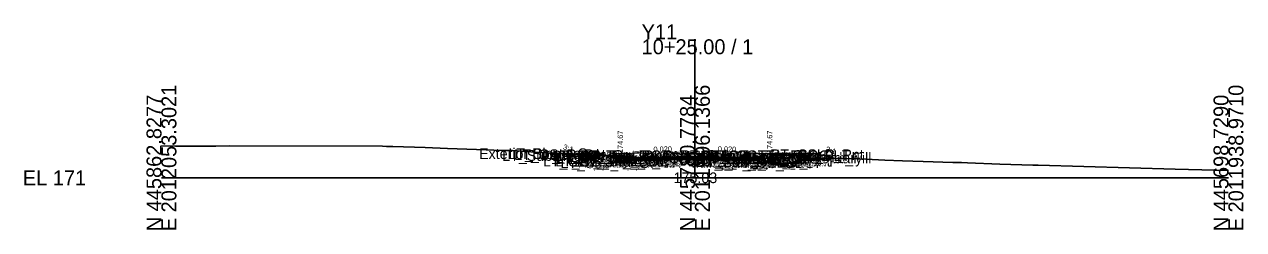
# Model space of a CAD drawing. Extents: x -26 to 203, y -10 to 3517.
# Drawn here: x -25.7 to 202.8, y 490.3 to 528.8 of the extents above; entities that cross this region are included whole.
import ezdxf

# ---------------------------------------------------------------- set-up
doc = ezdxf.new("R2010")
doc.units = 0
for name, color, linetype in [('Default', 7, 'Continuous'), ('Exist CMT Pavement', 7, 'Continuous'), ('Exist Cross Section Cell', 7, 'Continuous'), ('Exist XS Center Line Elevation Label', 7, 'Continuous'), ('Exist XS Ground Line', 7, 'Continuous'), ('Prop CMT Conc Surface', 7, 'Continuous'), ('Prop CMT Concrete Structures', 7, 'Continuous'), ('Prop CMT Pvmt Course 1', 7, 'Continuous'), ('Prop CMT Pvmt Course 1 CG', 7, 'Continuous'), ('Prop CMT Pvmt Course 1 Wedge', 7, 'Continuous'), ('Prop CMT Pvmt Course 2', 7, 'Continuous'), ('Prop CMT Pvmt Course 2 Wedge', 7, 'Continuous'), ('Prop CMT Pvmt Course 3', 7, 'Continuous'), ('Prop CMT Pvmt Course 3 Wedge', 7, 'Continuous'), ('Prop CMT Pvmt Surface', 7, 'Continuous'), ('Prop CMT Pvmt Wedge Surface 1', 7, 'Continuous'), ('Prop CMT Pvmt Wedge Surface 2', 7, 'Continuous'), ('Prop CMT Pvmt Wedge Surface 3', 7, 'Continuous'), ('Prop CMT Slope Grass', 7, 'Continuous'), ('Prop CMT Subgrade Earthwork', 7, 'Continuous'), ('Prop XS Earthwork Shape', 7, 'Continuous'), ('Prop XS Hydro Elevations', 7, 'Continuous'), ('Prop XS SE Text', 7, 'Continuous'), ('Prop XS Side Slope Text', 7, 'Continuous'), ('Scratch_Level_0', 7, 'Continuous')]:
    doc.layers.add(name, color=color, linetype=linetype)

msp = doc.modelspace()

# ---------------------------------------------------------------- linework, layer by layer
at = {"layer": 'Exist CMT Pavement'}
for points in [[(100, 504.03), (89.31, 503.79), (89, 503.83)], [(100, 504.03), (100.5, 504.04), (111, 503.73)]]:
    msp.add_lwpolyline(points, dxfattribs=at)
at = {"layer": 'Exist Cross Section Cell'}
for p, q in [((100, 500), (100, 526.01)), ((0, 500), (100, 500)), ((100, 500), (200, 500))]:
    msp.add_line(p, q, dxfattribs=at)
at = {"layer": 'Exist XS Ground Line'}
msp.add_lwpolyline([(0, 506), (2.65, 505.99), (8.91, 505.97), (10.21, 505.97), (12.8, 506), (41.41, 505.94), (42.21, 505.93), (43.37, 505.9), (49.4, 505.73), (53.6, 505.55), (60.86, 505.29), (63.76, 505.16), (65.79, 505.14), (70.95, 504.76), (85.86, 504.1), (87.28, 504.02), (87.87, 503.98), (89.31, 503.79), (89.65, 503.79), (96.56, 503.95), (100, 504.03), (100.5, 504.04), (112.54, 503.68), (113.41, 503.8), (128.42, 503.68), (130.84, 503.58), (135.6, 503.36), (138.92, 503.2), (142.79, 503.06), (148.34, 502.91), (149.97, 502.89), (151.11, 502.83), (157.16, 502.61), (163.3, 502.43), (164.34, 502.37), (190.01, 501.63), (200, 501.41)], dxfattribs=at)
at = {"layer": 'Prop CMT Conc Surface'}
for points in [[(86, 503.67), (86, 504.17), (85.5, 504.17)], [(88, 503.79), (86, 503.67)], [(112, 503.79), (114, 503.67)], [(114, 503.67), (114, 504.17), (114.5, 504.17)]]:
    msp.add_lwpolyline(points, dxfattribs=at)
at = {"layer": 'Prop CMT Concrete Structures'}
for points in [[(88, 503.79), (86, 503.67), (86, 504.17), (85.5, 504.17)], [(85.5, 504.17), (85.5, 503.16), (88, 503.21)], [(88, 503.21), (88, 503.79)], [(112, 503.79), (114, 503.67), (114, 504.17), (114.5, 504.17)], [(114.5, 504.17), (114.5, 503.16), (112, 503.21)], [(112, 503.21), (112, 503.79)]]:
    msp.add_lwpolyline(points, dxfattribs=at)
at = {"layer": 'Prop CMT Pvmt Course 1'}
for points in [[(100, 504.03), (88, 503.79)], [(88, 503.79), (88, 503.54)], [(88, 503.54), (89, 503.56)], [(89, 503.69), (100, 503.91)], [(89, 503.56), (89, 503.69)], [(100, 503.78), (100, 504.03)], [(100, 504.03), (112, 503.79)], [(100, 503.78), (100, 504.03)], [(100, 503.91), (100, 503.78), (100, 503.78)], [(111, 503.69), (100, 503.91)], [(100, 503.91), (100, 503.78), (100, 503.78)], [(111, 503.56), (111, 503.69)], [(112, 503.54), (111, 503.56)], [(112, 503.79), (112, 503.54)]]:
    msp.add_lwpolyline(points, dxfattribs=at)
at = {"layer": 'Prop CMT Pvmt Course 1 CG'}
for points in [[(88, 503.21), (85, 503.15), (84.7, 502.85)], [(84.7, 502.85), (88, 502.92)], [(88, 502.92), (88, 503.21)], [(112, 503.21), (115, 503.15), (115.3, 502.85)], [(112, 502.92), (112, 503.21)], [(115.3, 502.85), (112, 502.92)]]:
    msp.add_lwpolyline(points, dxfattribs=at)
at = {"layer": 'Prop CMT Pvmt Course 1 Wedge'}
for points in [[(100, 503.91), (89, 503.69)], [(100, 503.91), (111, 503.69)]]:
    msp.add_lwpolyline(points, dxfattribs=at)
at = {"layer": 'Prop CMT Pvmt Course 2'}
for points in [[(89, 503.56), (88, 503.54)], [(88, 503.54), (88, 503.29)], [(88, 503.29), (89, 503.31)], [(89, 503.31), (89, 503.56)], [(111, 503.31), (111, 503.56)], [(111, 503.56), (112, 503.54)], [(112, 503.29), (111, 503.31)], [(112, 503.54), (112, 503.29)]]:
    msp.add_lwpolyline(points, dxfattribs=at)
at = {"layer": 'Prop CMT Pvmt Course 2 Wedge'}
for points in [[(100, 503.78), (89, 503.56)], [(100, 503.78), (111, 503.56)]]:
    msp.add_lwpolyline(points, dxfattribs=at)
at = {"layer": 'Prop CMT Pvmt Course 3'}
for points in [[(89, 503.31), (88, 503.29)], [(88, 503.29), (88, 502.92)], [(88, 502.92), (89, 502.94)], [(89, 502.94), (89, 503.31)], [(111, 503.31), (112, 503.29)], [(111, 502.94), (111, 503.31)], [(112, 502.92), (111, 502.94)], [(112, 503.29), (112, 502.92)]]:
    msp.add_lwpolyline(points, dxfattribs=at)
at = {"layer": 'Prop CMT Pvmt Course 3 Wedge'}
for points in [[(100, 503.53), (89, 503.31)], [(100, 503.53), (111, 503.31)]]:
    msp.add_lwpolyline(points, dxfattribs=at)
at = {"layer": 'Prop CMT Pvmt Surface'}
for points in [[(100, 504.03), (88, 503.79)], [(100, 504.03), (112, 503.79)]]:
    msp.add_lwpolyline(points, dxfattribs=at)
at = {"layer": 'Prop CMT Pvmt Wedge Surface 1'}
for points in [[(88, 503.54), (88, 503.79)], [(89, 503.56), (88, 503.54)], [(100, 503.91), (89, 503.69)], [(89, 503.69), (89, 503.56)], [(100, 503.91), (111, 503.69)], [(111, 503.69), (111, 503.56)], [(111, 503.56), (112, 503.54)], [(112, 503.54), (112, 503.79)]]:
    msp.add_lwpolyline(points, dxfattribs=at)
at = {"layer": 'Prop CMT Pvmt Wedge Surface 2'}
for points in [[(88, 503.54), (88, 503.79)], [(100, 503.78), (88, 503.54)], [(100, 503.78), (112, 503.54)], [(112, 503.54), (112, 503.79)]]:
    msp.add_lwpolyline(points, dxfattribs=at)
at = {"layer": 'Prop CMT Pvmt Wedge Surface 3'}
for points in [[(88, 503.29), (88, 503.79)], [(100, 503.53), (88, 503.29)], [(100, 503.53), (112, 503.29)], [(112, 503.29), (112, 503.79)]]:
    msp.add_lwpolyline(points, dxfattribs=at)
at = {"layer": 'Prop CMT Slope Grass'}
for points in [[(85.5, 504.17), (76, 504.36), (75.39, 504.57)], [(114.5, 504.17), (124, 504.36), (125.97, 503.7)]]:
    msp.add_lwpolyline(points, dxfattribs=at)
at = {"layer": 'Prop CMT Subgrade Earthwork'}
for points in [[(88, 502.92), (84.7, 502.85), (83.34, 504.21)], [(89, 502.94), (88, 502.92)], [(89, 502.94), (89, 503.83)], [(111, 502.94), (111, 503.73)], [(111, 502.94), (112, 502.92)], [(112, 502.92), (115.3, 502.85), (116.66, 504.21)]]:
    msp.add_lwpolyline(points, dxfattribs=at)
at = {"layer": 'Prop XS Earthwork Shape'}
for points in [[(75.39, 504.57), (83.34, 504.21), (76, 504.36)], [(83.34, 504.21), (85.5, 504.12), (85.5, 503.16), (88, 503.21), (88, 503.79), (89, 503.81), (89, 502.94), (88, 502.92), (84.7, 502.85)], [(85.86, 504.1), (86, 504.09), (86, 503.67), (88, 503.79), (88, 503.21), (85.5, 503.16), (85.5, 504.12)], [(89, 503.81), (89, 503.83), (87.87, 503.98), (87.28, 504.02), (86, 504.09), (86, 503.67), (88, 503.79)], [(89.12, 503.81), (89, 503.81), (89, 503.83)], [(100.5, 504.04), (102.29, 503.98), (100, 504.03)], [(114.5, 503.79), (116.22, 503.78), (115.3, 502.85), (112, 502.92), (111, 502.94), (111, 503.73), (112, 503.7), (112, 503.21), (114.5, 503.16)], [(114.5, 503.79), (114.5, 503.16), (112, 503.21), (112, 503.7), (112.54, 503.68), (112.93, 503.73), (114, 503.67), (114, 503.79)], [(113.41, 503.8), (114, 503.79), (114, 503.67), (112.93, 503.73)], [(116.22, 503.78), (125.97, 503.7), (124, 504.36), (116.66, 504.21)]]:
    msp.add_lwpolyline(points, close=True, dxfattribs=at)

# ---------------------------------------------------------------- texts
at = {"layer": 'Default'}
msp.add_text('-', height=0.0001, dxfattribs=at).set_placement((0, 500))
at = {"layer": 'Exist Cross Section Cell'}
for s, p in [('Y11', (90, 526.01)), ('10+25.00 / 1', (90, 523.21)), ('EL 171', (-26, 498.6))]:
    msp.add_text(s, height=2.8, dxfattribs=at).set_placement(p)
for s, p in [('E 2012053.3021', (2.8, 490)), ('E 2011996.1366', (102.8, 490)), ('E 2011938.9710', (202.8, 490)), ('N 445862.8277', (0, 490)), ('N 445780.7784', (100, 490)), ('N 445698.7290', (200, 490))]:
    msp.add_text(s, height=2.8, rotation=90, dxfattribs=at).set_placement(p)
at = {"layer": 'Exist XS Center Line Elevation Label'}
msp.add_text('175.03', height=2, dxfattribs=at).set_placement((95.99, 499.03))
at = {"layer": 'Prop XS Hydro Elevations'}
for p in [(86.5, 504.67), (114.5, 504.67)]:
    msp.add_text('174.67', height=1, rotation=90, dxfattribs=at).set_placement(p)
at = {"layer": 'Prop XS SE Text'}
for rotation, p in [(1.1459, (92.23, 504.87)), (358.8541, (104.27, 504.94))]:
    msp.add_text('0.020', height=1, rotation=rotation, dxfattribs=at).set_placement(p)
at = {"layer": 'Prop XS Side Slope Text'}
for rotation, p in [(341.5718, (75.19, 505.42)), (341.5649, (124.4, 505.02))]:
    msp.add_text('3:1', height=1, rotation=rotation, dxfattribs=at).set_placement(p)
at = {"layer": 'Scratch_Level_0'}
for s, p in [('Exterior Boundary', (59.53, 503.55)), ('LT_Sub_Trench_Out_DLT', (63.87, 503.21)), ('LT_Slope_Cut', (65.02, 503.55)), ('LT_CSLP_Pnt', (66.14, 503.36)), ('LT_CG_Top_Face', (73.23, 503.17)), ('LT_CG_Top_BOC', (73.75, 503.17)), ('PV1_PGL', (94.44, 503.03)), ('RT_Sub_Trench_Out_DLT', (97.15, 503.21)), ('RT_CG_Top_Face', (101.18, 503.17)), ('RT_CG_Top_BOC', (102.7, 503.17)), ('RT_CSLP_Pnt', (114.09, 503.36)), ('LT_CG1_Shelf_Out', (71.52, 502.15)), ('LT_CG_Bot_BOC', (73.78, 502.16)), ('LT_PV_Sub_Tie_Out', (73.93, 502.76)), ('LT_CG_Top_Gut', (74.2, 502.67)), ('LT_Sub_OEOP', (74.78, 501.85)), ('LT_PV_OEEOP_EG', (76.51, 502.77)), ('LT_CG_Bot_IE', (77.88, 502.21)), ('LT_Sub_OEOT', (78.05, 501.92)), ('LT_PV2_OEOT', (78.14, 502.54)), ('LT_PV3_OEOT', (78.14, 502.29)), ('LT_Sub_OEEOP', (78.18, 501.94)), ('LT_PV2_OEEOP', (78.27, 502.56)), ('LT_PV3_OEEOP', (78.27, 502.31)), ('LT_PV1_OEOT', (78.71, 502.79)), ('LT_PV1_OEEOP', (78.84, 502.69)), ('RT_PV_IEEOP_EG', (88.11, 503)), ('LT_PV_IEEOP_EG', (88.16, 503)), ('RT_PV2_IEEOP', (89.87, 502.78)), ('RT_PV3_IEEOP', (89.87, 502.53)), ('LT_PV2_IEEOP', (89.92, 502.78)), ('LT_PV3_IEEOP', (89.92, 502.53)), ('RT_PV1_IEEOP', (90.44, 502.91)), ('LT_PV1_IEEOP', (90.49, 502.91)), ('PV2_PGL', (93.87, 502.78)), ('RT_PV_Sub_Tie_Out', (95.85, 502.69)), ('RT_PV_OEEOP_EG', (98.46, 502.69)), ('RT_Sub_OEEOP', (100.13, 501.94)), ('RT_PV2_OEEOP', (100.23, 502.56)), ('RT_PV3_OEEOP', (100.23, 502.31)), ('RT_PV1_OEEOP', (100.79, 502.69)), ('RT_CG1_Shelf_Out', (101.47, 502.15)), ('RT_CG_Bot_IE', (101.83, 502.21)), ('RT_Sub_OEOT', (102, 501.92)), ('RT_PV2_OEOT', (102.09, 502.54)), ('RT_PV3_OEOT', (102.09, 502.29)), ('RT_CG_Top_Gut', (102.15, 502.67)), ('RT_PV1_OEOT', (102.66, 502.79)), ('RT_CG_Bot_BOC', (102.73, 502.16)), ('RT_Sub_OEOP', (105.33, 501.85)), ('Exterior Boundary', (109.95, 502.75)), ('RT_Slope_Fill', (116.28, 502.75))]:
    msp.add_text(s, height=2, dxfattribs=at).set_placement(p)

doc.saveas('drawing.dxf')
